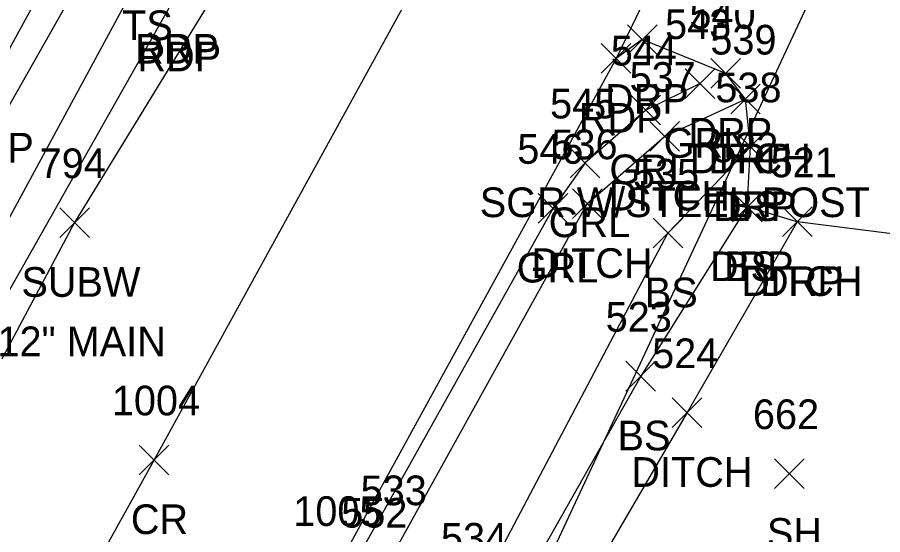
# Model space of a CAD drawing. Extents: x 1639430 to 1640195, y 612006 to 612917.
# Drawn here: x 1639849.6 to 1639907.9, y 612632.7 to 612667.5 of the extents above; entities that cross this region are included whole.
import ezdxf

# ---------------------------------------------------------------- set-up
doc = ezdxf.new("R2010")
doc.units = 0
for name, color, linetype in [('D_A', 7, 'Continuous'), ('D_I', 7, 'Continuous'), ('D_TIC', 7, 'Continuous'), ('DCP', 7, 'Continuous'), ('DD', 7, 'Continuous'), ('L_A', 7, 'Continuous'), ('L_I', 7, 'Continuous'), ('L_TIC', 7, 'Continuous'), ('LELB', 7, 'Continuous'), ('P_A', 7, 'Continuous'), ('P_I', 7, 'Continuous'), ('P_TIC', 7, 'Continuous'), ('PET', 7, 'Continuous'), ('PRC', 7, 'Continuous'), ('R_A', 7, 'Continuous'), ('R_C', 7, 'Continuous'), ('R_I', 7, 'Continuous'), ('R_TIC', 7, 'Continuous'), ('RDP', 7, 'Continuous'), ('RGR', 7, 'Continuous'), ('U_A', 7, 'Continuous'), ('U_C', 7, 'Continuous'), ('U_I', 7, 'Continuous'), ('U_TIC', 7, 'Continuous'), ('UW', 7, 'Continuous')]:
    doc.layers.add(name, color=color, linetype=linetype)

msp = doc.modelspace()

# ---------------------------------------------------------------- linework, layer by layer
at = {"layer": 'D_TIC'}
for points in [[(1639897.686, 612661.04), (1639899.686, 612663.04)], [(1639899.686, 612661.04), (1639897.686, 612663.04)], [(1639892.23, 612658.527), (1639894.23, 612660.527)], [(1639894.23, 612658.527), (1639892.23, 612660.527)], [(1639887.012, 612653.984), (1639889.012, 612655.984)], [(1639889.012, 612653.984), (1639887.012, 612655.984)], [(1639901.176, 612652.77), (1639903.176, 612654.77)], [(1639903.176, 612652.77), (1639901.176, 612654.77)], [(1639893.751, 612639.906), (1639895.751, 612641.906)], [(1639895.751, 612639.906), (1639893.751, 612641.906)]]:
    msp.add_lwpolyline(points, dxfattribs=at)
at = {"layer": 'DCP'}
msp.add_lwpolyline([(1639918.116, 612701.079), (1639877.218, 612613.44)], dxfattribs=at)
at = {"layer": 'DD'}
msp.add_lwpolyline([(1639902.176, 612653.77), (1639894.751, 612640.906), (1639885.255, 612624.678), (1639885.313, 612623.413), (1639886.889, 612621.636), (1639886.744, 612618.731), (1639879.193, 612622.233), (1639874.754, 612623.337), (1639875.09, 612631.669), (1639888.012, 612654.984), (1639893.23, 612659.527), (1639898.686, 612662.04)], dxfattribs=at)
at = {"layer": 'L_TIC'}
for points in [[(1639898.016, 612657.821), (1639900.016, 612659.821)], [(1639900.016, 612657.821), (1639898.016, 612659.821)], [(1639897.799, 612653.769), (1639899.799, 612655.769)], [(1639899.799, 612653.769), (1639897.799, 612655.769)], [(1639892.458, 612652.006), (1639894.458, 612654.006)], [(1639894.458, 612652.006), (1639892.458, 612654.006)], [(1639890.617, 612642.364), (1639892.617, 612644.364)], [(1639892.617, 612642.364), (1639890.617, 612644.364)], [(1639900.643, 612635.799), (1639902.643, 612637.799)], [(1639902.643, 612635.799), (1639900.643, 612637.799)]]:
    msp.add_lwpolyline(points, dxfattribs=at)
at = {"layer": 'LELB'}
for points in [[(1639856.893, 612675.516), (1639839.342, 612644.566), (1639837.164, 612635.143)], [(1639856.893, 612675.516), (1639858.232, 612671.011), (1639843.497, 612643.862), (1639837.164, 612635.143)], [(1639879.193, 612622.233), (1639880.51, 612628.471), (1639893.458, 612653.006), (1639899.016, 612658.821)], [(1639898.799, 612654.769), (1639891.617, 612643.364), (1639882.371, 612627.037), (1639882.132, 612621.728)]]:
    msp.add_lwpolyline(points, dxfattribs=at)
at = {"layer": 'P_TIC'}
for points in [[(1639888.959, 612663.779), (1639890.959, 612665.779)], [(1639890.959, 612663.779), (1639888.959, 612665.779)], [(1639857.802, 612636.722), (1639859.802, 612638.722)], [(1639859.802, 612636.722), (1639857.802, 612638.722)]]:
    msp.add_lwpolyline(points, dxfattribs=at)
at = {"layer": 'PET'}
for points in [[(1639899.845, 612685.235), (1639889.959, 612664.779)], [(1639860.191, 612668.905), (1639846.373, 612644.492), (1639830.054, 612614.558), (1639810.07, 612579.968), (1639792.174, 612548.775), (1639765.869, 612504.142)], [(1639889.959, 612664.779), (1639871.039, 612630.269), (1639855.317, 612602.067), (1639833.916, 612564.51), (1639815.495, 612533.184), (1639791.067, 612492.272)]]:
    msp.add_lwpolyline(points, dxfattribs=at)
at = {"layer": 'PRC'}
for points in [[(1639888.75, 612692.204), (1639858.802, 612637.722)], [(1639858.802, 612637.722), (1639842.594, 612608.574), (1639822.132, 612572.441), (1639804.172, 612540.707), (1639777.378, 612495.693)]]:
    msp.add_lwpolyline(points, dxfattribs=at)
at = {"layer": 'R_TIC'}
for points in [[(1639890.721, 612665.05), (1639892.721, 612667.05)], [(1639892.721, 612665.05), (1639890.721, 612667.05)], [(1639896.354, 612662.771), (1639898.354, 612664.771)], [(1639898.354, 612662.771), (1639896.354, 612664.771)], [(1639894.623, 612662.083), (1639896.623, 612664.083)], [(1639896.623, 612662.083), (1639894.623, 612664.083)], [(1639897.686, 612661.04), (1639899.686, 612663.04)], [(1639899.686, 612661.04), (1639897.686, 612663.04)], [(1639890.964, 612660.302), (1639892.964, 612662.302)], [(1639892.964, 612660.302), (1639890.964, 612662.302)], [(1639898.016, 612657.821), (1639900.016, 612659.821)], [(1639900.016, 612657.821), (1639898.016, 612659.821)], [(1639886.868, 612656.734), (1639888.868, 612658.734)], [(1639888.868, 612656.734), (1639886.868, 612658.734)], [(1639884.714, 612653.678), (1639886.714, 612655.678)], [(1639886.714, 612653.678), (1639884.714, 612655.678)], [(1639897.799, 612653.769), (1639899.799, 612655.769)], [(1639899.799, 612653.769), (1639897.799, 612655.769)], [(1639901.176, 612652.77), (1639903.176, 612654.77)], [(1639903.176, 612652.77), (1639901.176, 612654.77)]]:
    msp.add_lwpolyline(points, dxfattribs=at)
at = {"layer": 'RDP'}
for points in [[(1639825.663, 612646.251), (1639828.328, 612647.843), (1639835.112, 612646.854), (1639838.877, 612647.667), (1639847.556, 612662.758), (1639854.91, 612676.187), (1639857.768, 612677.278), (1639859.649, 612674.843), (1639860.03, 612669.42)], [(1639891.721, 612666.05), (1639889.959, 612664.779)], [(1639925.299, 612650.842), (1639902.176, 612653.77), (1639898.799, 612654.769), (1639899.016, 612658.821), (1639898.686, 612662.04), (1639897.354, 612663.771), (1639891.721, 612666.05)]]:
    msp.add_lwpolyline(points, dxfattribs=at)
at = {"layer": 'RGR'}
msp.add_lwpolyline([(1639895.623, 612663.083), (1639891.964, 612661.302), (1639887.868, 612657.734), (1639885.714, 612654.678), (1639867.25, 612621.742), (1639856.032, 612601.171), (1639838.745, 612570.685), (1639824.789, 612544.939), (1639823.114, 612538.523), (1639823.733, 612532.824)], dxfattribs=at)
at = {"layer": 'U_TIC'}
for points in [[(1639852.445, 612652.711), (1639854.445, 612654.711)], [(1639854.445, 612652.711), (1639852.445, 612654.711)]]:
    msp.add_lwpolyline(points, dxfattribs=at)
at = {"layer": 'UW'}
msp.add_lwpolyline([(1639878.262, 612694.255), (1639853.445, 612653.711), (1639817.159, 612585.632)], dxfattribs=at)

# ---------------------------------------------------------------- texts
at = {"layer": 'D_A'}
for p in [(1639894.922, 612657.04), (1639889.466, 612654.527), (1639884.248, 612649.984), (1639898.412, 612648.77), (1639890.987, 612635.906)]:
    msp.add_text('DITCH', height=2, dxfattribs=at).set_placement(p)
at = {"layer": 'D_I'}
for s, p in [('539', (1639896.316, 612665.04)), ('537', (1639890.868, 612662.527)), ('536', (1639885.594, 612657.984)), ('521', (1639900.381, 612656.77)), ('524', (1639892.389, 612643.906)), ('533', (1639872.728, 612634.669))]:
    msp.add_text(s, height=2, dxfattribs=at).set_placement(p)
at = {"layer": 'L_A'}
for s, p in [('TS', (1639856.641, 612666.011)), ('BS', (1639897.457, 612653.821)), ('BS', (1639897.24, 612649.769)), ('BS', (1639891.899, 612648.006)), ('BS', (1639890.058, 612638.364)), ('SH', (1639900.132, 612631.799))]:
    msp.add_text(s, height=2, dxfattribs=at).set_placement(p)
at = {"layer": 'L_I'}
for s, p in [('538', (1639896.654, 612661.821)), ('522', (1639896.437, 612657.769)), ('535', (1639891.096, 612656.006)), ('523', (1639889.255, 612646.364)), ('662', (1639899.187, 612639.799)), ('552', (1639871.422, 612633.158)), ('534', (1639878.148, 612631.471))]:
    msp.add_text(s, height=2, dxfattribs=at).set_placement(p)
at = {"layer": 'P_A'}
for s, p in [('RDP', (1639857.518, 612664.42)), ('RDP', (1639857.68, 612663.905)), ('RDP', (1639887.447, 612659.779)), ('CR', (1639857.235, 612632.722))]:
    msp.add_text(s, height=2, dxfattribs=at).set_placement(p)
at = {"layer": 'P_I'}
for s, p in [('1004', (1639855.951, 612640.722)), ('1005', (1639868.189, 612633.269))]:
    msp.add_text(s, height=2, dxfattribs=at).set_placement(p)
at = {"layer": 'R_A'}
for s, p in [('DRP', (1639857.518, 612664.42)), ('DRP', (1639889.209, 612661.05)), ('DRP', (1639894.842, 612658.771)), ('GRL', (1639893.167, 612658.083)), ('DRP', (1639845.044, 612657.758)), ('DRP', (1639896.174, 612657.04)), ('GRL', (1639889.507, 612656.302)), ('DRP', (1639896.504, 612653.821)), ('GRL', (1639885.412, 612652.734)), ('GRL', (1639883.257, 612649.678)), ('DRP', (1639896.287, 612649.769)), ('DRP', (1639899.664, 612648.77))]:
    msp.add_text(s, height=2, dxfattribs=at).set_placement(p)
at = {"layer": 'R_C'}
msp.add_text('SGR W/STEEL POST', height=2, dxfattribs=at).set_placement((1639880.765, 612654.083))
at = {"layer": 'R_I'}
for s, p in [('540', (1639894.905, 612666.771)), ('543', (1639893.261, 612666.083)), ('539', (1639896.316, 612665.04)), ('544', (1639889.602, 612664.302)), ('538', (1639896.654, 612661.821)), ('545', (1639885.506, 612660.734)), ('546', (1639883.296, 612657.678)), ('522', (1639896.437, 612657.769)), ('521', (1639900.381, 612656.77))]:
    msp.add_text(s, height=2, dxfattribs=at).set_placement(p)
at = {"layer": 'U_A'}
msp.add_text('SUBW', height=2, dxfattribs=at).set_placement((1639849.855, 612648.711))
at = {"layer": 'U_C'}
msp.add_text('12" MAIN', height=2, dxfattribs=at).set_placement((1639848.24, 612644.711))
at = {"layer": 'U_I'}
msp.add_text('794', height=2, dxfattribs=at).set_placement((1639851.083, 612656.711))

doc.saveas('drawing.dxf')
